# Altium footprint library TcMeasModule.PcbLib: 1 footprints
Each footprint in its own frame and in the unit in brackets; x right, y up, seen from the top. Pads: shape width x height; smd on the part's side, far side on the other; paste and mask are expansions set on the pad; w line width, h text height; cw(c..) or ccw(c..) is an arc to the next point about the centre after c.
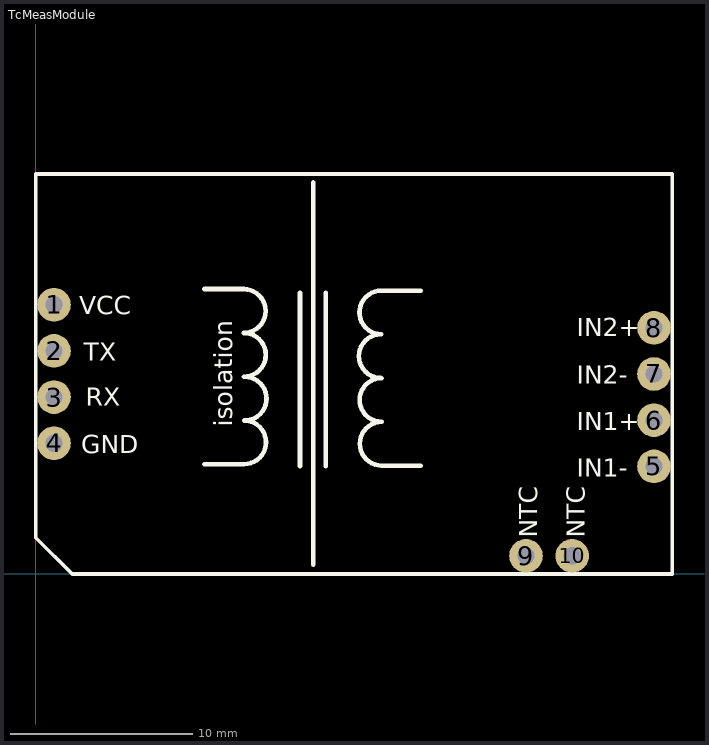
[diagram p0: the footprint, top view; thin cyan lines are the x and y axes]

## TcMeasModule [mm]
height 5
pads (10):
  round 1.85 hole 0.95: 1(1,14.81) 2(1,12.27) 3(1,9.73) 4(1,7.19) 5(34,5.92) 6(34,8.46) 7(34,11) 8(34,13.54) 9(26.96,1) 10(29.5,1)
Top Overlay:
  lines w0.2: 0,2 2,0 35,0 35,22 0,22 0,2
  lines w0.254: 9.28,6.044 11.46,6.044 ccw(c11.46,7.244) 11.46,8.444 ; 9.28,15.674 11.46,15.674 ; 11.44,13.264 ccw(c11.44,14.464) 11.44,15.664 ; 11.45,10.854 ccw(c11.45,12.054) 11.45,13.254 ; 11.49,8.444 ccw(c11.49,9.644) 11.49,10.844 ; 14.53,5.934 14.53,15.464 ; 15.25,0.5 15.25,21.53 ; 15.95,5.924 15.95,15.474 ; 18.97,10.784 cw(c18.97,11.984) 18.97,13.184 ; 19,5.954 21.18,5.954 ; 19,13.184 cw(c19,14.384) 19,15.584 21.18,15.584 ; 19.01,8.374 cw(c19.01,9.574) 19.01,10.774 ; 19.02,5.964 cw(c19.02,7.164) 19.02,8.364
  text "IN2+" at 29.76,13.07 h1
  text "IN2-" at 29.76,10.47 h1
  text "IN1+" at 29.76,7.92 h1
  text "IN1-" at 29.76,5.36 h1
  text "GND" at 2.507,6.63 h1
  text "RX" at 2.74,9.25 h1
  text "TX" at 2.623,11.72 h1
  text "VCC" at 2.39,14.28 h1
  text "isolation" at 10.81,8.099 h1
  text "NTC" at 27.58,1.99 h1
  text "NTC" at 30.2,1.99 h1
